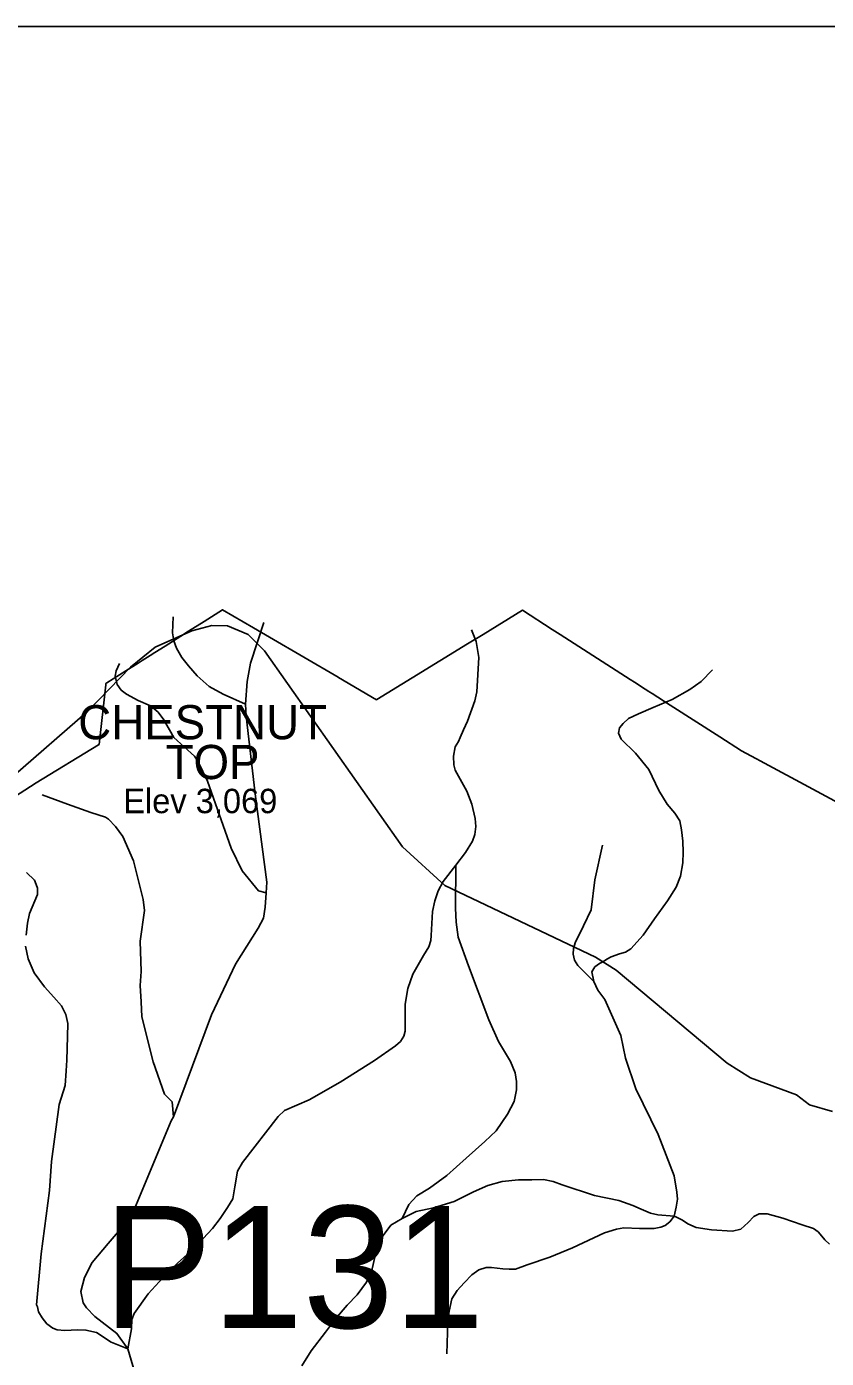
# Model space of a CAD drawing. Extents: x 884530 to 1028605, y 526725 to 653634.
# Drawn here: x 930133 to 932821, y 631169 to 635646 of the extents above; entities that cross this region are included whole.
import ezdxf

# ---------------------------------------------------------------- set-up
doc = ezdxf.new("R2010")
doc.units = 0
for name, color, linetype in [('Exist Boundary Political City Limit New', 7, 'Continuous'), ('Exist Boundary Political CountyLine', 7, 'Continuous'), ('Exist Geographical Mountain Summit Label', 7, 'Continuous'), ('Exist Road Non-System Type 51', 7, 'Continuous'), ('Exist Road Secondary Structure Pipe Number Label', 7, 'Continuous'), ('Exist Survey Geodetic Marker Label', 7, 'Continuous'), ('Map Preparation Boundary City Limit Buffer Line', 7, 'Continuous'), ('Map Preparation Inset Cut Line', 7, 'Continuous')]:
    doc.layers.add(name, color=color, linetype=linetype)

msp = doc.modelspace()

# ---------------------------------------------------------------- linework, layer by layer
at = {"layer": 'Exist Boundary Political City Limit New'}
msp.add_lwpolyline([(932967.1, 632979.9), (932599.1, 633177.6), (932586.1, 633184.6), (932567.7, 633194.6), (932535.6, 633212), (932463.2, 633258.2), (932296.1, 633365.1), (932235.6, 633403.8), (932227.7, 633408.9), (932224, 633411.2), (932212.5, 633418.5), (932175.8, 633442.1), (932161.9, 633451.1), (931926.7, 633602.1), (931899.4, 633619.6), (931799.4, 633683.9), (931667.3, 633602.9), (931615.1, 633570.9), (931428.9, 633456.8), (931310.2, 633384.1), (931309.1, 633383.4), (931180.9, 633458.2), (931179.4, 633459.2), (930949, 633593.7), (930895.1, 633625.1), (930791.5, 633685.6), (930729, 633646.2), (930676.8, 633613.3), (930650.5, 633596.7), (930623.2, 633579.4), (930597.9, 633563.5), (930563.1, 633541.5), (930548.2, 633532.1), (930521.2, 633515.1), (930507.8, 633506.6), (930466.7, 633480.6), (930402.5, 633440.1), (930399, 633437.9), (930398.5, 633433.7), (930376, 633232.8), (930374.6, 633231.9), (930164.8, 633103.6), (930072.4, 633044.1)], dxfattribs=at)
at = {"layer": 'Exist Boundary Political CountyLine'}
msp.add_lwpolyline([(932841.2, 631998.7), (932764.8, 632021.8), (932720.5, 632055.5), (932566, 632112.4), (932487.9, 632162.1), (932115, 632474.7), (932044.9, 632517.4), (931538, 632758.9), (931395.9, 632888.6), (930932.5, 633547.6), (930877.5, 633602.7), (930808.2, 633631.1), (930755, 633632.9), (930687.5, 633615.1), (930565, 633560), (930481.5, 633492.5), (930338.6, 633345.1), (930086.5, 633124.9), (929947.1, 633030.7)], dxfattribs=at)
at = {"layer": 'Exist Road Non-System Type 51'}
for points in [[(930868.4, 633368), (930793.5, 633402.3), (930746.8, 633427.9), (930705.5, 633463.9), (930676.3, 633497.4), (930654.4, 633525.6), (930636.8, 633556.4), (930628, 633581.1), (930622.7, 633608.4), (930624.8, 633661.4)], [(930868.4, 633368), (930873.6, 633444.5), (930885.1, 633506.3), (930930.6, 633643)], [(931575.2, 632827.1), (931607.5, 632870.3), (931631.3, 632908.4), (931639.8, 632930.3), (931643.1, 632957.1), (931640.9, 632984), (931629.1, 633032.6), (931612.9, 633076.1), (931573.1, 633146), (931568.5, 633164.7), (931567.9, 633193.8), (931573.1, 633225), (931584, 633243.2), (931589.8, 633256.7), (931601.6, 633281.7), (931614.3, 633310.9), (931639.4, 633379.6), (931645.7, 633410.2), (931653, 633525.7), (931644.2, 633578.5), (931628.5, 633618.7)], [(930938.2, 632734.6), (930912.2, 632741.4), (930857.2, 632807.7), (930820.2, 632884.7), (930740.2, 633109.9), (930709.5, 633174.6), (930697, 633193.1), (930628, 633256), (930593.6, 633315.4), (930575.3, 633341.1), (930548.7, 633363.2), (930508, 633381.2), (930468.6, 633402.1), (930450.2, 633415.4), (930437, 633434.5), (930430.2, 633462.7), (930433.9, 633479.9), (930445.3, 633504.8)], [(932039.5, 632436), (932033, 632469.1), (932043, 632485), (932058.9, 632496.6), (932071.8, 632503.8), (932083.4, 632511), (932097.5, 632519.2), (932125.7, 632529.7), (932146, 632535.1), (932164.3, 632545.6), (932205.8, 632591.4), (932243.7, 632646.7), (932287, 632707.3), (932315.8, 632753.5), (932330.9, 632790.4), (932338.8, 632835.3), (932339.7, 632870.5), (932338.8, 632908.4), (932334.4, 632945.4), (932328.2, 632976.2), (932311.7, 633001.9), (932285.9, 633032), (932258.3, 633078.6), (932224, 633148.8), (932179.3, 633203.5), (932131.7, 633250.2), (932122.5, 633270.3), (932125.4, 633289.1), (932138, 633303.7), (932155.6, 633319.6), (932190, 633336.3), (932238.4, 633356.6), (932302.7, 633383.8), (932361.7, 633417.3), (932400.4, 633444.5), (932438.4, 633484.2)], [(930938.2, 632734.6), (930939.7, 632770.2), (930901, 633067.2), (930870.6, 633327.9), (930868.4, 633368)], [(930626.4, 631981.7), (930621.4, 632031.9), (930595.7, 632057.8), (930557.8, 632166), (930520.4, 632317.3), (930517.2, 632367.8), (930514.8, 632422.3), (930517.4, 632469.9), (930513.8, 632571.6), (930528.6, 632675.3), (930524.7, 632711.3), (930491.9, 632842.2), (930456.2, 632923.3), (930431.6, 632956.8), (930408.3, 632981.5), (930398.3, 632988.2), (930348.9, 633004.4), (930270.6, 633032), (930185.1, 633063.6)], [(932039.5, 632436), (931985.1, 632490.1), (931974.6, 632507.7), (931970, 632528), (931970.8, 632547.4), (931976.3, 632566), (932005.1, 632623.3), (932030.9, 632676.6), (932042.9, 632778), (932068.7, 632894.9)], [(931575.2, 632827.1), (931532.7, 632772), (931516.4, 632741.3), (931504.7, 632707.4), (931496.9, 632671.1), (931493.1, 632590.4), (931491, 632573.8), (931484.3, 632552.5), (931466.5, 632524), (931430.7, 632460.5), (931414.6, 632412.2), (931404.8, 632360.2), (931404.8, 632308.8), (931405.2, 632269.2), (931400.4, 632252.1), (931389.1, 632234.9), (931373.2, 632219.7), (931301.9, 632170.4), (931186.9, 632097.3), (931082, 632038.9), (930999.9, 632002.7), (930978.4, 631982), (930858.8, 631828), (930841.7, 631798.2), (930832.7, 631746.4), (930825.5, 631705.8), (930807.9, 631676.1), (930782.8, 631639.1), (930758, 631605.8), (930693.1, 631537.3), (930639.4, 631489.1), (930594.3, 631443.6), (930578.2, 631426.5), (930540.7, 631386.7), (930494.4, 631320.5), (930486.3, 631300.6), (930485.5, 631268.3), (930472.6, 631201.4)], [(931394.9, 631639.9), (931417.7, 631686.9), (931444.2, 631716.1), (931487.2, 631741.8), (931545, 631784.2), (931610.3, 631842.6), (931672.8, 631898.8), (931711, 631934.2), (931749.2, 631989.9), (931771.4, 632033), (931779.8, 632071.9), (931779, 632100.4), (931774.9, 632129.1), (931759.6, 632166.9), (931718.4, 632235), (931686.5, 632307.7), (931618.4, 632488.4), (931583.9, 632585.2), (931576.1, 632635.2), (931574.2, 632682.3), (931575.2, 632827.1)], [(930130.9, 632591.6), (930135.4, 632632.7), (930142.7, 632665.1), (930168.7, 632728.1), (930169.3, 632749.7), (930164.9, 632762.7), (930159.2, 632776.9), (930131.7, 632802)], [(930626.4, 631981.7), (930754.5, 632323.6), (930834.5, 632494.4), (930910.7, 632615.1), (930929.1, 632648.9), (930934.9, 632685.7), (930938.2, 632734.6)], [(930472.6, 631201.4), (930417, 631224.1), (930367.1, 631255.8), (930331.9, 631264.6), (930303.8, 631265.3), (930261.2, 631263.1), (930234.8, 631265.4), (930221, 631270.6), (930200.4, 631286), (930185.1, 631305.2), (930172.8, 631325.6), (930169.5, 631342.8), (930166, 631349.5), (930181.9, 631521.3), (930209.2, 631733.9), (930215.9, 631830.9), (930242.2, 632023.1), (930261.9, 632086.2), (930265.5, 632135.5), (930267.5, 632171.7), (930270, 632251.7), (930270.8, 632295.1), (930264.9, 632325.3), (930249.4, 632353.9), (930224.4, 632383.4), (930192.7, 632418.7), (930157.5, 632465.8), (930137.6, 632512.1), (930129.3, 632554.7)], [(932309.6, 631646.9), (932316, 631678), (932320.4, 631704.4), (932318.7, 631727.6), (932309.6, 631782.9), (932255.5, 631921.8), (932180.2, 632075.3), (932146, 632178.6), (932130.6, 632254.9), (932076.7, 632376.1), (932052.4, 632406.8), (932039.5, 632436)], [(930472.6, 631201.4), (930436, 631253.1), (930362.1, 631310.6), (930333.4, 631339.6), (930322.8, 631356.2), (930314.8, 631393.8), (930327.5, 631441.2), (930352.8, 631491.8), (930406.6, 631555.1), (930460.3, 631618.3), (930495.1, 631672.1), (930618.8, 631967.8), (930626.4, 631981.7)], [(931394.9, 631639.9), (931442.3, 631663.3), (931500.8, 631675), (931570.3, 631696.4), (931634.6, 631728.9), (931683.4, 631750.4), (931731.3, 631763.4), (931786.6, 631769.2), (931831.4, 631769.9), (931870.4, 631770.5), (931902.3, 631764), (931932.7, 631753), (932041.3, 631717.2), (932123.1, 631700.4), (932170.6, 631682.8), (932198.5, 631671.1), (932229.5, 631657.6), (932254.5, 631651.9), (932309.6, 631646.9)], [(932309.6, 631646.9), (932294.5, 631627.9), (932278.8, 631616.1), (932264.2, 631610.4), (932241.9, 631606.3), (932192.4, 631605.8), (932140.2, 631607.9), (932115.4, 631604.2), (932075.1, 631591.2), (931967.3, 631540.4), (931891.2, 631509.4), (931815.2, 631483.3), (931775.6, 631469.4), (931754.7, 631468.8), (931733.3, 631470.8), (931695.7, 631475), (931677.6, 631475), (931652.6, 631466.6), (931629.6, 631450.6), (931603.3, 631422.9), (931579.7, 631397.9), (931562.3, 631369.4), (931553.3, 631327.7), (931548.8, 631291.7), (931545, 631184.5)], [(932831.9, 631553.2), (932816.5, 631567.4), (932805.4, 631579.9), (932793.5, 631594.5), (932777.6, 631605.6), (932740.1, 631618.8), (932674.8, 631640.4), (932622, 631654.9), (932595.5, 631655.6), (932577.5, 631645.9), (932558.1, 631626.4), (932533.7, 631604.2), (932505.2, 631597.3), (932435.1, 631601.4), (932383.6, 631609.7), (932355.8, 631621.6), (932337.1, 631634.1), (932317, 631644.5), (932309.6, 631646.9)], [(931057.3, 631144.6), (931088.9, 631194.2), (931136.9, 631257.2), (931171, 631301.9), (931210.7, 631348.5), (931244.1, 631383.3), (931275.3, 631425.6), (931292.3, 631460), (931311.1, 631543.8), (931330.9, 631582), (931357.3, 631617.4), (931394.9, 631639.9)], [(930699.8, 630094.8), (930667.5, 630165), (930640.8, 630221.5), (930621.9, 630274.5), (930599.5, 630346.9), (930593.2, 630429.2), (930586.8, 630546.2), (930586.8, 630742.3), (930577.4, 630846.6), (930555.5, 630947.8), (930501.4, 631105.9), (930472.6, 631201.4)]]:
    msp.add_lwpolyline(points, dxfattribs=at)
at = {"layer": 'Map Preparation Boundary City Limit Buffer Line'}
msp.add_lwpolyline([(932967.1, 632979.9), (932599.1, 633177.6), (932586.1, 633184.6), (932567.7, 633194.6), (932535.6, 633212), (932463.2, 633258.2), (932296.1, 633365.1), (932235.6, 633403.8), (932227.7, 633408.9), (932224, 633411.2), (932212.5, 633418.5), (932175.8, 633442.1), (932161.9, 633451.1), (931926.7, 633602.1), (931899.4, 633619.6), (931799.4, 633683.9), (931667.3, 633602.9), (931615.1, 633570.9), (931428.9, 633456.8), (931310.2, 633384.1), (931309.1, 633383.4), (931180.9, 633458.2), (931179.4, 633459.2), (930949, 633593.7), (930895.1, 633625.1), (930791.5, 633685.6), (930729, 633646.2), (930676.8, 633613.3), (930650.5, 633596.7), (930623.2, 633579.4), (930597.9, 633563.5), (930563.1, 633541.5), (930548.2, 633532.1), (930521.2, 633515.1), (930507.8, 633506.6), (930466.7, 633480.6), (930402.5, 633440.1), (930399, 633437.9), (930398.5, 633433.7), (930376, 633232.8), (930374.6, 633231.9), (930164.8, 633103.6), (930072.4, 633044.1)], dxfattribs=at)
at = {"layer": 'Map Preparation Inset Cut Line'}
msp.add_lwpolyline([(929019.7, 608590.9), (973281.3, 608590.9), (973281.3, 635645.7), (929019.7, 635645.7)], close=True, dxfattribs=at)

# ---------------------------------------------------------------- texts
at = {"layer": 'Exist Geographical Mountain Summit Label'}
for s, p in [('CHESTNUT', (930306.2, 633250.3)), ('TOP', (930600, 633116.5))]:
    msp.add_text(s, height=114.83, dxfattribs=at).set_placement(p)
at = {"layer": 'Exist Road Secondary Structure Pipe Number Label'}
msp.add_text('P131', height=410.1, dxfattribs=at).set_placement((930390.3, 631271.6))
at = {"layer": 'Exist Survey Geodetic Marker Label'}
msp.add_text('Elev 3,069', height=82.02, dxfattribs=at).set_placement((930457.2, 633001.9))

doc.saveas('drawing.dxf')
